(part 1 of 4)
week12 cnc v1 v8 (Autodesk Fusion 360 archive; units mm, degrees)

design "week12 cnc v1" references "dollhome_wall_cnc", "Component3"
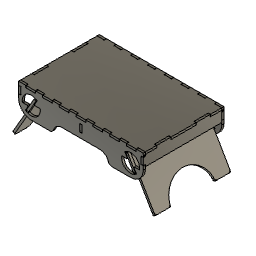
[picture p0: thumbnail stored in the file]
parameter "toplength" = 695.427
sketch "Sketch1" plane through (0, 0, 0) normal (0, 1, 0) x axis (1, 0, 0)
  line L1 (695.4269, 0) -> (0, 0)
  line L2 (695.4269, -141.0037) -> (695.4269, 0)
  line L3 (0, -141.0037) -> (695.4269, -141.0037)
  line L4 (0, 0) -> (0, -141.0037)
  line L5 (192.7135, 0) -> (22.7135, 0)
  line L6 (347.7135, -50) -> (242.7135, -50)
  line L7 (347.7135, 0) -> (347.7135, -141.0037)
  line L8 (502.7135, 0) -> (672.7135, 0)
  line L9 (347.7135, -50) -> (452.7135, -50)
  arc A1 centre (242.7135, 0) radius 50 clockwise from (242.7135, -50) to (192.7135, 0)
  arc A2 centre (452.7135, 0) radius 50 clockwise from (502.7135, 0) to (452.7135, -50)
  circle C1 centre (624.9251, -70.5018) radius 50
  circle C2 centre (70.5018, -70.5018) radius 50
  circle C3 centre (624.9251, -70.5018) radius 70.5018
  circle C4 centre (70.5018, -70.5018) radius 70.5018
  point P1 (0, 0)
  point P2 (0, 0)
  point P6 (22.7135, 0)
  point P7 (192.7135, 0)
  point P11 (347.7135, -141.0037)
  point P12 (347.7135, 0)
  point P13 (672.7135, 0)
  point P15 (502.7135, 0)
  point P8 (242.7135, -50)
  point P16 (452.7135, -50)
  point P10 (347.7135, -50)
  point P17 (347.7135, -50)
  point P9 (242.7135, 0)
  point P14 (452.7135, 0)
  point P4 (695.4269, -141.0037)
  point P5 (0, -141.0037)
  horizontal L1
  vertical L2
  horizontal L3
  vertical L4
  coincident P1 P2
  coincident L1 P6
  coincident L1 P7
  midpoint L3 P11
  midpoint L1 P12
  symmetric P6 L7 P13
  symmetric P7 L7 P15
  symmetric P8 L7 P16
  symmetric A1 L7 A2
  symmetric P10 L7 P17
  symmetric L7 C1 C2
  coincident L1 P9
  tangent A2 L9
  coincident P10 P17
  perpendicular L6 L7
  concentric C1 C3
  tangent L1 C3
  tangent L3 C3
  tangent L2 C3
  concentric C2 C4
  tangent L1 C4
  dimension "d6" diameter C1 = 100
  dimension "d100" distance L1 L6 = 50
  dimension "d101" distance P9 P14 = 210
  dimension "d102" distance P4 P5 = 695.4269
sketch "Sketch5" plane through (0, 0, 0) normal (0, 0, 1) x axis (1, 0, 0)
  line L1 (695.427, 0) -> (0, 0)
  line L2 (695.427, 450) -> (695.427, 0)
  line L3 (0, 450) -> (695.427, 450)
  line L4 (0, 0) -> (0, 450)
  line L5 (695.427, 225) -> (0, 225)
  line L6 (347.7135, 0) -> (347.7135, 450)
  point P1 (0, 0)
  point P2 (0, 0)
  point P6 (0, 225)
  point P7 (695.427, 225)
  point P8 (347.7135, 450)
  point P9 (347.7135, 0)
  point P3 (695.427, 0)
  point P4 (695.427, 450)
  horizontal L1
  vertical L2
  horizontal L3
  vertical L4
  coincident P1 P2
  coincident L4 P6
  coincident L2 P7
  perpendicular L2 L5
  coincident L3 P8
  coincident L1 P9
  perpendicular L1 L6
  midpoint L5 L6
  dimension "d104" distance L2 L4 = 695.427 (= "toplength")
  dimension "d110" distance P3 P4 = 450
extrude "Extrude1" new body sketch "Sketch1" profile of L1 L2 L3 L4 L5 A1 L6 A2 L8 L9 C1 C2 C3 C4 no distance stored
extrude "Extrude1" sketch "Sketch5" profile of L1 L2 L3 L4 no distance stored
work_plane "WorkPlane2" AlongDistance 225
mirror_component "MirrorComponent2"
derived_instance "DerivedInstance2"
sketch "Sketch6" plane through (0, 0, 0) normal (0, 1, 0) x axis (1, 0, 0)
  line L1 (618.9251, -23.0018) -> (630.9251, -23.0018)
  line L2 (618.9251, -118.0018) -> (618.9251, -23.0018)
  line L3 (630.9251, -118.0018) -> (618.9251, -118.0018)
  line L4 (630.9251, -23.0018) -> (630.9251, -118.0018)
  line L5 (618.9251, -118.0018) -> (630.9251, -23.0018)
  line L6 (630.9251, -118.0018) -> (618.9251, -23.0018)
  line L7 (347.7135, 0) -> (347.7135, -141.0037)
  line L8 (64.5018, -118.0018) -> (76.5018, -118.0018)
  line L9 (76.5018, -118.0018) -> (76.5018, -23.0018)
  line L10 (64.5018, -23.0018) -> (64.5018, -118.0018)
  line L11 (76.5018, -23.0018) -> (64.5018, -23.0018)
  line L12 (64.5018, -118.0018) -> (76.5018, -23.0018)
  line L13 (76.5018, -118.0018) -> (64.5018, -23.0018)
  line L14 (0, 0) -> (0, -150)
  point P6 (624.9251, -70.5018)
  point P7 (624.9251, -70.5018)
  point P2 (630.9251, -23.0018)
  point P12 (64.5018, -23.0018)
  point P3 (618.9251, -23.0018)
  point P15 (76.5018, -23.0018)
  point P4 (618.9251, -118.0018)
  point P10 (76.5018, -118.0018)
  point P5 (630.9251, -118.0018)
  point P11 (64.5018, -118.0018)
  point P14 (70.5018, -70.5018)
  point P13 (70.5018, -70.5018)
  point P1 (0, 0)
  point P17 (0, 0)
  horizontal L1
  perpendicular L1 L2
  parallel L1 L3
  parallel L2 L4
  coincident L5 P6
  coincident L6 P6
  coincident P6 P7
  symmetric P2 L7 P12
  symmetric P3 L7 P15
  symmetric P4 L7 P10
  symmetric P5 L7 P11
  symmetric P6 L7 P14
  symmetric P7 L7 P13
  vertical L14
  coincident P1 P17
  dimension "d112" distance P3 P4 = 95
  dimension "d113" distance P4 P5 = 12 (= "Linear Dimension-3")
sketch "Sketch9" plane through (0, 0, 0) normal (1, 0, 0) x axis (0, 1, 0)
  line L1 (76.9446, 118.0018) -> (0, 118.0018)
  line L2 (80, 23.0018) -> (0, 23.0018)
  line L3 (117.9773, 70.5018) -> (0, 70.5018)
  point P2 (0, 118.0018)
  point P3 (0, 118.0018)
  point P5 (0, 23.0018)
  point P6 (0, 23.0018)
  point P8 (0, 70.5018)
  point P9 (0, 70.5018)
  coincident P2 P3
  horizontal L1
  coincident P5 P6
  horizontal L2
  coincident P8 P9
  horizontal L3
work_plane "WorkPlane3" AlongDistance 70.502
sketch "Sketch12" plane through (70.502, 0, 0) normal (1, 0, 0) x axis (0, 1, 0)
  line L1 (436, 135) -> (14, 135)
  line L2 (436, -165) -> (436, 135)
  line L3 (14, -165) -> (436, -165)
  line L4 (14, 135) -> (14, -165)
  line L5 (450, 141.0037) -> (0, 141.0037)
  line L6 (438, 70.5018) -> (438, 0)
  line L7 (225, -154.225) -> (225, 154.225)
  line L8 (0, 0) -> (450, 0)
  line L9 (12, 0) -> (12, 141.0037)
  line L10 (12, 0) -> (0, 0)
  line L11 (0, 0) -> (0, 141.0037)
  arc A1 centre (225.1382, -175.6217) radius 125.5882 clockwise from (100, -165) to (350.2765, -165)
  point P15 (100, -165)
  point P14 (350.2765, -165)
  point P18 (12, 141.0037)
  point P19 (12, 0)
  point P1 (0, 0)
  point P20 (0, 0)
  point P2 (14, 135)
  point P17 (14, 135)
  point P3 (436, 135)
  point P4 (436, -165)
  point P11 (225, -154.225)
  point P16 (225.1382, -175.6217)
  horizontal L1
  vertical L2
  horizontal L3
  vertical L4
  perpendicular L3 L7
  midpoint L7 L8
  coincident L3 P15
  coincident L3 P14
  coincident L5 P18
  coincident L8 P19
  coincident P1 P20
  vertical L9
  coincident P2 P17
  dimension "d120" distance L1 L5 = 6.0037
  dimension "d121" distance P3 P4 = 300
  dimension "d122" distance L2 L6 = 2
  dimension "d123" distance P11 P16 = 21.3972
  dimension "d124" distance P14 P15 = 250.2765
  dimension "d380" distance L9 L11 = 12
  dimension "d381" distance L4 L9 = 2
extrude "Extrude1" new body sketch "Sketch12" profile of L1 L2 L3 L4 L8 A1 no distance stored
extrude "Extrude2" new body sketch "Sketch6" profile of L8 L9 L10 L11 to an object
work_plane "WorkPlane4" AlongDistance 347.714
mirror_component "MirrorComponent3"
derived_instance "DerivedInstance3"
joint "Assemble8" alignAngle 210 alignOffsetX 0 alignOffsetY 0 alignOffsetZ 0
sketch "Sketch13" plane through (0, 0, 0) normal (0, 0, 1) x axis (1, 0, 0)
  line L1 (40, 12) -> (0, 12)
  line L2 (40, 0) -> (40, 12)
  line L3 (0, 0) -> (40, 0)
  line L4 (0, 12) -> (0, 0)
  line L5 (0, 0) -> (0, 450)
  line L6 (695.427, 0) -> (0, 0)
  line L7 (133.6429, 12) -> (93.6429, 12)
  line L8 (93.6429, 12) -> (93.6429, 0)
  line L9 (133.6429, 0) -> (133.6429, 12)
  line L10 (93.6429, 0) -> (133.6429, 0)
  line L11 (227.2857, 12) -> (187.2857, 12)
  line L12 (187.2857, 12) -> (187.2857, 0)
  line L13 (227.2857, 0) -> (227.2857, 12)
  line L14 (187.2857, 0) -> (227.2857, 0)
  line L15 (320.9286, 12) -> (280.9286, 12)
  line L16 (280.9286, 12) -> (280.9286, 0)
  line L17 (320.9286, 0) -> (320.9286, 12)
  line L18 (280.9286, 0) -> (320.9286, 0)
  line L19 (414.5714, 12) -> (374.5714, 12)
  line L20 (374.5714, 12) -> (374.5714, 0)
  line L21 (414.5714, 0) -> (414.5714, 12)
  line L22 (374.5714, 0) -> (414.5714, 0)
  line L23 (508.2143, 12) -> (468.2143, 12)
  line L24 (468.2143, 12) -> (468.2143, 0)
  line L25 (508.2143, 0) -> (508.2143, 12)
  line L26 (468.2143, 0) -> (508.2143, 0)
  line L27 (601.8571, 12) -> (561.8571, 12)
  line L28 (561.8571, 12) -> (561.8571, 0)
  line L29 (601.8571, 0) -> (601.8571, 12)
  line L30 (561.8571, 0) -> (601.8571, 0)
  line L31 (695.5, 12) -> (655.5, 12)
  line L32 (655.5, 12) -> (655.5, 0)
  line L33 (695.5, 0) -> (695.5, 12)
  line L34 (655.5, 0) -> (695.5, 0)
  line L35 (695.427, 225) -> (0, 225)
  line L36 (320.9286, 450) -> (320.9286, 438)
  line L37 (468.2143, 438) -> (468.2143, 450)
  line L38 (227.2857, 438) -> (187.2857, 438)
  line L39 (40, 450) -> (40, 438)
  line L40 (93.6429, 450) -> (133.6429, 450)
  line L41 (133.6429, 450) -> (133.6429, 438)
  line L42 (133.6429, 438) -> (93.6429, 438)
  line L43 (93.6429, 438) -> (93.6429, 450)
  line L44 (0, 450) -> (40, 450)
  line L45 (40, 438) -> (0, 438)
  line L46 (0, 438) -> (0, 450)
  line L47 (561.8571, 450) -> (601.8571, 450)
  line L48 (227.2857, 450) -> (227.2857, 438)
  line L49 (508.2143, 450) -> (508.2143, 438)
  line L50 (655.5, 438) -> (655.5, 450)
  line L51 (695.5, 450) -> (695.5, 438)
  line L52 (414.5714, 438) -> (374.5714, 438)
  line L53 (601.8571, 450) -> (601.8571, 438)
  line L54 (655.5, 450) -> (695.5, 450)
  line L55 (414.5714, 450) -> (414.5714, 438)
  line L56 (320.9286, 438) -> (280.9286, 438)
  line L57 (695.5, 438) -> (655.5, 438)
  line L58 (508.2143, 438) -> (468.2143, 438)
  line L59 (601.8571, 438) -> (561.8571, 438)
  line L60 (374.5714, 438) -> (374.5714, 450)
  line L61 (468.2143, 450) -> (508.2143, 450)
  line L62 (561.8571, 438) -> (561.8571, 450)
  line L63 (187.2857, 438) -> (187.2857, 450)
  line L64 (187.2857, 450) -> (227.2857, 450)
  line L65 (280.9286, 450) -> (320.9286, 450)
  line L66 (695.427, 450) -> (0, 450)
  line L67 (280.9286, 438) -> (280.9286, 450)
  line L68 (374.5714, 450) -> (414.5714, 450)
  point P4 (40, 0)
  point P2 (0, 12)
  point P1 (0, 0)
  point P57 (0, 450)
  point P67 (0, 438)
  point P3 (40, 12)
  point P56 (40, 438)
  point P58 (40, 450)
  point P5 (0, 0)
  point P55 (0, 450)
  point P7 (0, 0)
  point P68 (0, 450)
  point P8 (695.427, 0)
  point P59 (695.427, 450)
  point P9 (93.6429, 12)
  point P54 (93.6429, 438)
  point P10 (133.6429, 12)
  point P53 (133.6429, 438)
  point P11 (93.6429, 0)
  point P52 (93.6429, 450)
  point P12 (133.6429, 0)
  point P66 (133.6429, 450)
  point P13 (187.2857, 12)
  point P65 (187.2857, 438)
  point P14 (227.2857, 12)
  point P64 (227.2857, 438)
  point P15 (187.2857, 0)
  point P63 (187.2857, 450)
  point P16 (227.2857, 0)
  point P62 (227.2857, 450)
  point P17 (280.9286, 12)
  point P61 (280.9286, 438)
  point P18 (320.9286, 12)
  point P49 (320.9286, 438)
  point P19 (280.9286, 0)
  point P60 (280.9286, 450)
  point P20 (320.9286, 0)
  point P44 (320.9286, 450)
  point P21 (374.5714, 12)
  point P73 (374.5714, 438)
  point P22 (414.5714, 12)
  point P46 (414.5714, 438)
  point P23 (374.5714, 0)
  point P70 (374.5714, 450)
  point P24 (414.5714, 0)
  point P72 (414.5714, 450)
  point P25 (468.2143, 12)
  point P47 (468.2143, 438)
  point P26 (508.2143, 12)
  point P51 (508.2143, 438)
  point P27 (468.2143, 0)
  point P71 (468.2143, 450)
  point P28 (508.2143, 0)
  point P69 (508.2143, 450)
  point P29 (561.8571, 12)
  point P50 (561.8571, 438)
  point P30 (601.8571, 12)
  point P45 (601.8571, 438)
  point P31 (561.8571, 0)
  point P41 (561.8571, 450)
  point P32 (601.8571, 0)
  point P40 (601.8571, 450)
  point P33 (655.5, 12)
  point P48 (655.5, 438)
  point P34 (695.5, 12)
  point P42 (695.5, 438)
  point P35 (655.5, 0)
  point P39 (655.5, 450)
  point P36 (695.5, 0)
  point P43 (695.5, 450)
  horizontal L1
  vertical L2
  horizontal L3
  vertical L4
  coincident P4 L6
  coincident P2 L5
  symmetric P1 L35 P57
  symmetric P2 L35 P67
  symmetric P3 L35 P56
  symmetric P4 L35 P58
  symmetric P5 L35 P55
  symmetric P7 L35 P68
  symmetric P8 L35 P59
  symmetric P9 L35 P54
  symmetric P10 L35 P53
  symmetric P11 L35 P52
  symmetric P12 L35 P66
  symmetric P13 L35 P65
  symmetric P14 L35 P64
  symmetric P15 L35 P63
  symmetric P16 L35 P62
  symmetric P17 L35 P61
  symmetric P18 L35 P49
  symmetric P19 L35 P60
  symmetric P20 L35 P44
  symmetric P21 L35 P73
  symmetric P22 L35 P46
  symmetric P23 L35 P70
  symmetric P24 L35 P72
  symmetric P25 L35 P47
  symmetric P26 L35 P51
  symmetric P27 L35 P71
  symmetric P28 L35 P69
  symmetric P29 L35 P50
  symmetric P30 L35 P45
  symmetric P31 L35 P41
  symmetric P32 L35 P40
  symmetric P33 L35 P48
  symmetric P34 L35 P42
  symmetric P35 L35 P39
  symmetric P36 L35 P43
  dimension "d138" distance L2 L4 = 40
  dimension "d377" distance L1 L3 = 12 (= "Linear Dimension-3")
  dimension "d141" R-Pattern1-uDistance = 655.5
  dimension "d142" R-Pattern1-vDistance = 0
sketch "Sketch14" plane through (0, 0, 0) normal (0, 0, 1) x axis (1, 0, 0)
  line L1 (695.4269, 0) -> (0, 0)
  line L2 (695.4269, 12) -> (695.4269, 0)
  line L3 (0, 12) -> (695.4269, 12)
  line L4 (0, 0) -> (0, 12)
extrude "Extrude2" sketch "Sketch13" profile of L1 L2 L3 L4 L5 L6 L7 L8 L9 L10 L11 L12 L13 L14 L15 L16 L17 L18 L19 L20 L21 L22 L23 L24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 no distance stored
extrude "Extrude1" sketch "Sketch13" profile of L5 L36 L37 L38 L39 L40 L41 L42 L43 L44 L45 L46 L47 L48 L49 L50 L51 L52 L53 L54 L55 L56 L57 L58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 no distance stored
sketch "Sketch24" plane through (0, 0, 153.0037) normal (0, 0, 1) x axis (-1, 0, 0)
  line L1 (0, -450) -> (-695.427, -450)
  line L2 (0, 0) -> (0, -450)
  line L3 (-695.427, 0) -> (0, 0)
  line L4 (-695.427, -450) -> (-695.427, 0)
joint "Assemble9" alignAngle 0 alignOffsetX 0 alignOffsetY 0 alignOffsetZ 0 RotateMinimum 30 RotateMaximum 90 RotateRest 30
extrude "Extrude2" sketch "Sketch13" profile of L1 L2 L3 L4 L5 L6 L7 L8 L9 L10 L11 L12 L13 L14 L15 L16 L17 L18 L19 L20 L21 L22 L23 L24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 no distance stored
position "Position2" RotateAboutZ -60 RotateAboutZ 30
sketch "Sketch15" plane through (0, 0, 0) normal (0, 1, 0) x axis (1, 0, 0)
  line L1 (13.1164, -32.418) -> (38.1164, -32.4224)
  line L2 (0.6125, -54.0664) -> (13.1164, -32.418)
  line L3 (13.1087, -75.7192) -> (0.6125, -54.0664)
  line L4 (38.1087, -75.7237) -> (13.1087, -75.7192)
  line L5 (50.6125, -54.0752) -> (38.1087, -75.7237)
  line L6 (38.1164, -32.4224) -> (50.6125, -54.0752)
  line L7 (127.8936, -108.5819) -> (102.8936, -108.5909)
  line L8 (140.3858, -86.9267) -> (127.8936, -108.5819)
  line L9 (127.878, -65.2806) -> (140.3858, -86.9267)
  line L10 (102.878, -65.2896) -> (127.878, -65.2806)
  line L11 (90.3858, -86.9447) -> (102.878, -65.2896)
  line L12 (102.8936, -108.5909) -> (90.3858, -86.9447)
  line L13 (0.6125, -54.0664) -> (50.6125, -54.0752)
  line L14 (140.3858, -86.9267) -> (90.3858, -86.9447)
  circle C1 centre (70.5018, -70.5018) radius 50
  point P9 (102.8936, -108.5909)
  point P2 (38.1164, -32.4224)
  point P7 (50.6125, -54.0752)
  point P14 (90.3858, -86.9447)
  coincident P9 C1
  dimension "d158" distance P2 P7 = 25
  dimension "d159" distance P9 P14 = 25
extrude "Extrude4" new body sketch "Sketch15" profile of L1 L6 L12 C1 L13 L14 no distance stored
position "Position3" RotateAboutZ -90
extrude "Extrude5" add of existing geometry blind 7
extrude "Extrude6" add of existing geometry blind 3
extrude "Extrude7" add of existing geometry blind 7
extrude "Extrude8" add of existing geometry blind 3
mirror "Mirror1" mirrorStitchTolerance 0.1
work_plane "WorkPlane5"
mirror "Mirror2" mirrorStitchTolerance 0.1
mirror "Mirror3" mirrorStitchTolerance 0.1
component_from_bodies "Body->Comp4"
component_from_bodies "Body->Comp5"
component_from_bodies "Body->Comp6"
component_from_bodies "Body->Comp7"
component_from_bodies "Body->Comp8"
component_from_bodies "Body->Comp9"
component_from_bodies "Body->Comp10"
component_from_bodies "Body->Comp11"
work_plane "WorkPlane7"
mirror "Mirror2" mirrorStitchTolerance 0.1
combine "Combine1"
combine "Combine1"
combine "Combine3"
fillet "Fillet1" radius 5
fillet "Fillet2" radius 5
fillet "Fillet1" radius 20
work_plane "WorkPlane8"
work_plane "WorkPlane9"
mirror "Mirror1" mirrorStitchTolerance 0.1
mirror "Mirror3" mirrorStitchTolerance 0.1
sketch "Sketch26" plane through (347.7135, 0, 0) normal (-1, 0, 0) x axis (0, -1, 0)
  line L1 (-438, 70.5018) -> (-438, 141.0037)
  line L2 (-12, 70.5018) -> (-12, 141.0037)
  line L3 (-450, 118.306) -> (-438, 118.306)
  line L4 (-450, 78.306) -> (-450, 118.306)
  line L5 (-438, 78.306) -> (-450, 78.306)
  line L6 (-12, 133.306) -> (-438, 133.306)
  line L7 (-12, 70.5018) -> (-438, 70.5018)
  line L8 (-225, 70.5018) -> (-225, 133.306)
  line L9 (0, 118.306) -> (-12, 118.306)
  line L10 (0, 78.306) -> (0, 118.306)
  line L11 (-12, 78.306) -> (0, 78.306)
  point P6 (-438, 118.306)
  point P9 (-438, 78.306)
  point P10 (-438, 133.306)
  point P11 (-12, 133.306)
  point P3 (-438, 70.5018)
  point P12 (-438, 70.5018)
  point P5 (-12, 70.5018)
  point P13 (-12, 70.5018)
  point P14 (-225, 133.306)
  point P15 (-225, 70.5018)
  point P16 (-12, 118.306)
  point P7 (-450, 118.306)
  point P17 (0, 118.306)
  point P8 (-450, 78.306)
  point P18 (0, 78.306)
  point P19 (-12, 78.306)
  coincident L1 P6
  perpendicular L1 L3
  perpendicular L3 L4
  coincident L1 P9
  perpendicular L1 L5
  coincident L1 P10
  coincident L2 P11
  perpendicular L2 L6
  coincident P3 P12
  coincident P5 P13
  midpoint L6 P14
  midpoint L7 P15
  symmetric P6 L8 P16
  symmetric P7 L8 P17
  symmetric P8 L8 P18
  symmetric P9 L8 P19
  dimension "d394" distance P6 L6 = 15
  dimension "d395" distance P6 P7 = 12 (= "Linear Dimension-3")
  dimension "d398" distance P7 P8 = 40
extrude "Extrude15" new body sketch "Sketch26" profile of L1 L2 L3 L4 L5 L6 L7 L9 L10 L11 no distance stored
combine "Combine2"
combine "Combine3"
sketch "Sketch27" plane through (0, 0, 0) normal (-1, 0, 0) x axis (0, -1, 0)
  line L1 (-12, 153.0037) -> (-12, 141.0037)
  line L2 (-438, 153.0037) -> (-12, 153.0037)
  line L3 (-438, 141.0037) -> (-438, 153.0037)
  line L4 (-12, 153.0037) -> (-438, 153.0037)
  line L5 (-450, 70.5018) -> (-450, 153.0037)
  line L6 (0, 70.5018) -> (0, 153.0037)
  line L7 (-225, -203.8085) -> (-225, 153.0037)
  line L8 (0, 111.7528) -> (-450, 111.7528)
  line L9 (-375, 141.0037) -> (-375, 153.0037)
  line L10 (-295, 141.0037) -> (-295, 153.0037)
  line L11 (-155, 141.0037) -> (-155, 153.0037)
  line L12 (-75, 141.0037) -> (-75, 153.0037)
  line L13 (-438, 131.7528) -> (-450, 131.7528)
  line L14 (-438, 91.7528) -> (-450, 91.7528)
  line L15 (-12, 131.7528) -> (0, 131.7528)
  line L16 (-12, 91.7528) -> (0, 91.7528)
  line L17 (-438, 141.0037) -> (-438, 131.7528)
  line L18 (-438, 141.0037) -> (-375, 141.0037)
  line L19 (-155, 141.0037) -> (-295, 141.0037)
  line L20 (-438, 81.7528) -> (-438, 91.7528)
  line L21 (-12, 81.7528) -> (-438, 81.7528)
  line L22 (-12, 91.7528) -> (-12, 81.7528)
  line L23 (-450, 91.7528) -> (-450, 131.7528)
  line L24 (0, 91.7528) -> (0, 131.7528)
  line L25 (-12, 131.7528) -> (-12, 141.0037)
  line L26 (-12, 141.0037) -> (-75, 141.0037)
  point P12 (-225, 153.0037)
  point P14 (-450, 111.7528)
  point P15 (0, 111.7528)
  point P16 (-375, 153.0037)
  point P18 (-295, 153.0037)
  point P20 (-155, 153.0037)
  point P22 (-75, 153.0037)
  point P24 (-450, 131.7528)
  point P26 (-450, 91.7528)
  point P28 (0, 131.7528)
  point P25 (-438, 131.7528)
  point P29 (-12, 131.7528)
  point P30 (0, 91.7528)
  point P27 (-438, 91.7528)
  point P31 (-12, 91.7528)
  point P5 (-438, 141.0037)
  point P32 (-438, 141.0037)
  point P33 (-438, 141.0037)
  point P2 (-12, 141.0037)
  point P36 (-12, 141.0037)
  point P17 (-375, 141.0037)
  point P19 (-295, 141.0037)
  point P21 (-155, 141.0037)
  point P23 (-75, 141.0037)
  midpoint L4 P12
  midpoint L5 P14
  midpoint L6 P15
  coincident L2 P16
  coincident L4 P18
  coincident L4 P20
  coincident L4 P22
  coincident L5 P24
  perpendicular L5 L13
  coincident L5 P26
  perpendicular L5 L14
  symmetric L7 P24 P28
  symmetric L7 P25 P29
  symmetric L7 P26 P30
  symmetric L7 P27 P31
  coincident P5 P32
  coincident P5 P33
  perpendicular L17 L18
  vertical L7
  vertical L12
  perpendicular L14 L20
  perpendicular L20 L21
  vertical L22
  coincident P2 P36
  dimension "d399" distance P24 P25 = 12 (= "Linear Dimension-2")
  dimension "d400" distance P26 P27 = 12 (= "Linear Dimension-3")
  dimension "d401" distance L8 L13 = 20
  dimension "d402" distance L8 L14 = 20
  dimension "d403" distance L7 P18 = 70
  dimension "d404" distance P12 P20 = 70
  dimension "d405" distance L9 L10 = 80
  dimension "d406" distance L11 L12 = 80
  dimension "d407" distance P16 P17 = 12 (= "Linear Dimension-10")
  dimension "d408" distance P18 P19 = 12 (= "Linear Dimension-11")
  dimension "d409" distance P20 P21 = 12 (= "Linear Dimension-12")
  dimension "d410" distance P22 P23 = 12 (= "Linear Dimension-13")
  dimension "d411" distance P27 L21 = 10
extrude "Extrude16" new body sketch "Sketch27" profile of L2 L4 L5 L6 L9 L10 L11 L12 L13 L14 L15 L16 L17 L18 L19 L20 L21 L22 L23 L24 L25 L26 no distance stored
combine "Combine4"
combine "Combine4"
combine "Combine5"
mirror "Mirror4" mirrorStitchTolerance 0.1
combine "Combine5"
combine "Combine6"
combine "Combine7"
component_from_bodies "Body->Comp1"
component_from_bodies "Body->Comp2"
component_from_bodies "Body->Comp1"
component_from_bodies "Body->Comp2"
component_from_bodies "Body->Comp14"
component_from_bodies "Body->Comp15"
component_from_bodies "Body->Comp16"
step "Arrange7" AngleFromX 0 Priority 500 AngleFromX 0 Priority 500 AngleFromX 0 Priority 500 AngleFromX 0 Priority 500 AngleFromX 0 Priority 500 AngleFromX 0 Priority 500 AngleFromX 0 Priority 500 AngleFromX 0 Priority 500 originOffsetX 1300 originOffsetY 0 envelopeLength 2438.4 envelopeWidth 1219.2 envelopeSpacing 0 grainDirection 0 objectSpacing 15 frameWidth 30 placementClearance 0
fillet "Fillet1" radius 15
work_plane "WorkPlane10"
sketch "Sketch28" plane through (1368.1164, 62.4225, 0) normal (0, 0, 1) x axis (1, 0, 0)
  line L1 (-0.0175, 0) -> (0, 0)
  line L2 (0, 0) -> (12.4962, 21.6528)
  line L3 (2.5978, 1.5005) -> (0, 0)
  circle C1 centre (2.5978, 1.5005) radius 3
  point P2 (0, 0)
  point P5 (0, 0)
  point P6 (2.5978, 1.5005)
  coincident P2 P5
  coincident P5 C1
  dimension "d448" distance P5 P6 = 3 (= "6 mm / 2")
sweep "Sweep1" sketch "Sketch28" TwistAngle 0 TaperAngle 0
work_plane "WorkPlane11"
sketch "Sketch29" plane through (1351.3995, 91.0701, 0) normal (0, 0, 1) x axis (1, 0, 0)
  line L1 (0, 0) -> (29.2118, 0.0052)
  line L2 (54.353, 22.763) -> (0, 0)
  arc A1 centre (49.1024, 9.4318) radius 50 clockwise from (0, 0) to (81.4941, 47.5208)
  point P3 (0, 0)
  point P6 (0, 0)
  coincident P3 P6
base_feature "Base Feature10" bodies "Dogbones"
combine "Combine6"
base_feature "Base Feature11" bodies "Dogbones (1)"
combine "Combine1"
base_feature "Base Feature12" bodies "Dogbones (2)"
combine "Combine2"
base_feature "Base Feature13" bodies "Dogbones (3)"
combine "Combine3"
base_feature "Base Feature14" bodies "Dogbones (4)"
combine "Combine4"
base_feature "Base Feature15" bodies "Dogbones (5)"
combine "Combine7"
base_feature "Base Feature16" bodies "Dogbones (6)"
combine "Combine5"
base_feature "Base Feature17" bodies "Dogbones (7)"
combine "Combine8"
base_feature "Base Feature18" bodies "Dogbones (8)"
combine "Combine1"
base_feature "Base Feature19" bodies "Dogbones (9)"
combine "Combine9"
base_feature "Base Feature20" bodies "Dogbones (10)"
combine "Combine1"
base_feature "Base Feature21" bodies "Dogbones (11)"
combine "Combine10"
base_feature "Base Feature22" bodies "Dogbones (12)"
combine "Combine1"
sketch "Sketch30" plane through (0, 0, 12) normal (0, 0, 1) x axis (-1, 0, 0)
  line L1 (-1342.073, -688.5332) -> (-1342.073, -719.9761)
  line L2 (-1330.0731, -684.2546) -> (-1337.7945, -684.2546)
  line L3 (-1330.0731, -675.0037) -> (-1330.0731, -684.2546)
  line L4 (-1330, -675.0037) -> (-1330.0731, -675.0037)
  line L5 (-1330, -663.0037) -> (-1330, -675.0037)
  line L6 (-1370, -663.0037) -> (-1330, -663.0037)
  line L7 (-1370, -675.0037) -> (-1370, -663.0037)
  line L8 (-1419.3643, -675.0037) -> (-1370, -675.0037)
  line L9 (-1423.6429, -663.0037) -> (-1423.6429, -670.7251)
  line L10 (-1463.6429, -663.0037) -> (-1423.6429, -663.0037)
  line L11 (-1463.6429, -670.7251) -> (-1463.6429, -663.0037)
  line L12 (-1513.0072, -675.0037) -> (-1467.9214, -675.0037)
  line L13 (-1517.2857, -663.0037) -> (-1517.2857, -670.7251)
  line L14 (-1557.2857, -663.0037) -> (-1517.2857, -663.0037)
  line L15 (-1557.2857, -670.7251) -> (-1557.2857, -663.0037)
  line L16 (-1606.65, -675.0037) -> (-1561.5643, -675.0037)
  line L17 (-1610.9286, -663.0037) -> (-1610.9286, -670.7251)
  line L18 (-1650.9286, -663.0037) -> (-1610.9286, -663.0037)
  line L19 (-1650.9286, -670.7251) -> (-1650.9286, -663.0037)
  line L20 (-1700.2929, -675.0037) -> (-1655.2072, -675.0037)
  line L21 (-1704.5715, -663.0037) -> (-1704.5715, -670.7251)
  line L22 (-1744.5715, -663.0037) -> (-1704.5715, -663.0037)
  line L23 (-1744.5715, -670.7251) -> (-1744.5715, -663.0037)
  line L24 (-1793.9358, -675.0037) -> (-1748.85, -675.0037)
  line L25 (-1798.2143, -663.0037) -> (-1798.2143, -670.7251)
  line L26 (-1838.2143, -663.0037) -> (-1798.2143, -663.0037)
  line L27 (-1838.2143, -670.7251) -> (-1838.2143, -663.0037)
  line L28 (-1887.5786, -675.0037) -> (-1842.4929, -675.0037)
  line L29 (-1891.8572, -663.0037) -> (-1891.8572, -670.7251)
  line L30 (-1931.8572, -663.0037) -> (-1891.8572, -663.0037)
  line L31 (-1931.8572, -670.7251) -> (-1931.8572, -663.0037)
  line L32 (-1981.2215, -675.0037) -> (-1936.1357, -675.0037)
  line L33 (-1985.5, -663.0037) -> (-1985.5, -670.7251)
  line L34 (-2025.5, -663.0037) -> (-1985.5, -663.0037)
  line L35 (-2025.5, -684.2546) -> (-2025.5, -663.0037)
  line L36 (-2013.5, -684.2546) -> (-2025.5, -684.2546)
  line L37 (-2013.5, -724.2546) -> (-2013.5, -684.2546)
  line L38 (-2025.5, -724.2546) -> (-2013.5, -724.2546)
  line L39 (-2025.5, -745.5056) -> (-2025.5, -724.2546)
  line L40 (-1849.8686, -816.0074) -> (-1954.9982, -816.0074)
  line L41 (-1572.7866, -766.0074) -> (-1782.7866, -766.0074)
  line L42 (-1400.575, -816.0074) -> (-1505.7045, -816.0074)
  line L43 (-1330.0731, -724.2546) -> (-1330.0731, -745.5055)
  line L44 (-1337.7945, -724.2546) -> (-1330.0731, -724.2546)
  line L45 (-1987.3837, -783.585) -> (-1987.4012, -783.585)
  line L46 (-1974.8875, -761.9321) -> (-1987.3837, -783.585)
  line L47 (-1974.8888, -754.9321) -> (-1974.8875, -761.9321)
  line L48 (-2004.1006, -754.9373) -> (-1974.8888, -754.9321)
  line L49 (-1935.1142, -729.0627) -> (-1924.5451, -710.7716)
  line L50 (-1935.1168, -736.0627) -> (-1935.1142, -729.0627)
  line L51 (-1909.749, -736.0718) -> (-1935.1168, -736.0627)
  line L52 (-1420.4563, -736.0627) -> (-1449.6772, -736.0732)
  line L53 (-1420.4588, -729.0627) -> (-1420.4563, -736.0627)
  line L54 (-1432.9666, -707.4165) -> (-1420.4588, -729.0627)
  line L55 (-1447.7974, -729.0725) -> (-1447.7973, -729.0725)
  line L56 (-1380.6843, -754.9321) -> (-1351.4726, -754.9373)
  line L57 (-1380.6855, -761.9321) -> (-1380.6843, -754.9321)
  line L58 (-1368.1894, -783.585) -> (-1380.6855, -761.9321)
  line L59 (-1368.1719, -783.585) -> (-1368.1894, -783.585)
  line L60 (-1671.7865, -737.7014) -> (-1671.7865, -697.7014)
  line L61 (-1683.7865, -737.7014) -> (-1671.7865, -737.7014)
  line L62 (-1683.7865, -697.7014) -> (-1683.7865, -737.7014)
  line L63 (-1671.7865, -697.7014) -> (-1683.7865, -697.7014)
  line L64 (-1434.7562, -704.3195) -> (-1431.5367, -709.8912)
  line L65 (-1455.022, -712.8044) -> (-1434.7562, -704.3195)
  line L66 (-1450.26, -732.3009) -> (-1455.022, -712.8044)
  line L67 (-1436.646, -727.5949) -> (-1450.26, -732.3009)
  line L68 (-1431.5367, -709.8912) -> (-1436.646, -727.5949)
  arc A1 centre (-1339.9337, -722.1154) radius 3.0254 clockwise from (-1337.7945, -724.2546) to (-1342.073, -719.9761)
  arc A2 centre (-1339.9337, -686.3939) radius 3.0254 clockwise from (-1342.073, -688.5332) to (-1337.7945, -684.2546)
  arc A3 centre (-1421.5036, -672.8644) radius 3.0254 clockwise from (-1419.3643, -675.0037) to (-1423.6429, -670.7251)
  arc A4 centre (-1465.7822, -672.8644) radius 3.0254 clockwise from (-1463.6429, -670.7251) to (-1467.9214, -675.0037)
  arc A5 centre (-1515.1465, -672.8644) radius 3.0254 clockwise from (-1513.0072, -675.0037) to (-1517.2857, -670.7251)
  arc A6 centre (-1559.425, -672.8644) radius 3.0254 clockwise from (-1557.2857, -670.7251) to (-1561.5643, -675.0037)
  arc A7 centre (-1608.7893, -672.8644) radius 3.0254 clockwise from (-1606.65, -675.0037) to (-1610.9286, -670.7251)
  arc A8 centre (-1653.0679, -672.8644) radius 3.0254 clockwise from (-1650.9286, -670.7251) to (-1655.2072, -675.0037)
  arc A9 centre (-1702.4322, -672.8644) radius 3.0254 clockwise from (-1700.2929, -675.0037) to (-1704.5715, -670.7251)
  arc A10 centre (-1746.7107, -672.8644) radius 3.0254 clockwise from (-1744.5715, -670.7251) to (-1748.85, -675.0037)
  arc A11 centre (-1796.075, -672.8644) radius 3.0254 clockwise from (-1793.9358, -675.0037) to (-1798.2143, -670.7251)
  arc A12 centre (-1840.3536, -672.8644) radius 3.0254 clockwise from (-1838.2143, -670.7251) to (-1842.4929, -675.0037)
  arc A13 centre (-1889.7179, -672.8644) radius 3.0254 clockwise from (-1887.5786, -675.0037) to (-1891.8572, -670.7251)
  arc A14 centre (-1933.9965, -672.8644) radius 3.0254 clockwise from (-1931.8572, -670.7251) to (-1936.1357, -675.0037)
  arc A15 centre (-1983.3607, -672.8644) radius 3.0254 clockwise from (-1981.2215, -675.0037) to (-1985.5, -670.7251)
  arc A16 centre (-1954.9982, -745.5055) radius 70.5018 clockwise from (-1954.9982, -816.0074) to (-2025.5, -745.5056)
  arc A17 centre (-1849.8686, -796.0074) radius 20 clockwise from (-1830.7023, -801.7217) to (-1849.8686, -816.0074)
  arc A18 centre (-1782.7866, -816.0074) radius 50 clockwise from (-1830.7023, -801.7217) to (-1782.7866, -766.0074)
  arc A19 centre (-1572.7866, -816.0074) radius 50 clockwise from (-1572.7866, -766.0074) to (-1524.8708, -801.7217)
  arc A20 centre (-1505.7045, -796.0074) radius 20 clockwise from (-1505.7045, -816.0074) to (-1524.8708, -801.7217)
  arc A21 centre (-1400.575, -745.5055) radius 70.5018 clockwise from (-1330.0731, -745.5055) to (-1400.575, -816.0074)
  arc A22 centre (-1907.8233, -738.4052) radius 3.0254 clockwise from (-1909.749, -736.0718) to (-1905.2949, -740.0665)
  arc A23 centre (-1954.9982, -745.5055) radius 50 clockwise from (-1905.2949, -740.0665) to (-1987.4012, -783.585)
  arc A24 centre (-1954.9982, -745.5055) radius 50 clockwise from (-2004.1006, -754.9373) to (-1925.8038, -704.9138)
  arc A25 centre (-1925.5877, -707.9315) radius 3.0254 clockwise from (-1925.8038, -704.9138) to (-1924.5451, -710.7716)
  arc A26 centre (-1400.575, -745.5055) radius 50 clockwise from (-1368.1719, -783.585) to (-1449.6772, -736.0732)
  arc A27 centre (-1400.5749, -745.5055) radius 50 clockwise from (-1447.7973, -729.0725) to (-1432.9666, -707.4165)
  arc A28 centre (-1400.575, -745.5055) radius 50 clockwise from (-1447.7974, -729.0725) to (-1351.4726, -754.9373)
  point P117 (-1431.5367, -709.8912)
  coincident L54 P117
extrude "Extrude2" add sketch "Sketch30" profile of A27 L55 A28 L64 to an object
base_feature "Base Feature23" bodies "Dogbones (13)"
combine "Combine2"
base_feature "Base Feature24" bodies "Dogbones (14)"
combine "Combine3"
base_feature "Base Feature25" bodies "Dogbones (15)"
combine "Combine4"
base_feature "Base Feature26" bodies "Dogbones (16)"
combine "Combine6"
base_feature "Base Feature27" bodies "Dogbones (17)"
combine "Combine5"
base_feature "Base Feature28" bodies "Dogbones1"
combine "Combine2"
base_feature "Base Feature29" bodies "Dogbones1 (1)"
combine "Combine1"
base_feature "Base Feature30" bodies "Dogbones1 (2)"
combine "Combine6"
sketch "Sketch31" plane through (0, 0, 12) normal (0, 0, 1) x axis (-1, 0, 0)
  line L1 (-2013.5, -719.9761) -> (-2013.5, -688.5332)
  line L2 (-2025.5, -724.2546) -> (-2017.7786, -724.2546)
  line L3 (-2025.5, -745.5056) -> (-2025.5, -724.2546)
  line L4 (-1849.8686, -816.0074) -> (-1954.9982, -816.0074)
  line L5 (-1572.7866, -766.0074) -> (-1782.7866, -766.0074)
  line L6 (-1400.575, -816.0074) -> (-1505.7045, -816.0074)
  line L7 (-1330.0731, -724.2546) -> (-1330.0731, -745.5055)
  line L8 (-1337.7945, -724.2546) -> (-1330.0731, -724.2546)
  line L9 (-1342.073, -688.5332) -> (-1342.073, -719.9761)
  line L10 (-1330.0731, -684.2546) -> (-1337.7945, -684.2546)
  line L11 (-1330.0731, -679.2823) -> (-1330.0731, -684.2546)
  line L12 (-1330, -663.0037) -> (-1330, -674.933)
  line L13 (-1370, -663.0037) -> (-1330, -663.0037)
  line L14 (-1370, -670.7251) -> (-1370, -663.0037)
  line L15 (-1419.3643, -675.0037) -> (-1374.2786, -675.0037)
  line L16 (-1423.6429, -663.0037) -> (-1423.6429, -670.7251)
  line L17 (-1463.6429, -663.0037) -> (-1423.6429, -663.0037)
  line L18 (-1463.6429, -670.7251) -> (-1463.6429, -663.0037)
  line L19 (-1513.0072, -675.0037) -> (-1467.9214, -675.0037)
  line L20 (-1517.2857, -663.0037) -> (-1517.2857, -670.7251)
  line L21 (-1557.2857, -663.0037) -> (-1517.2857, -663.0037)
  line L22 (-1557.2857, -670.7251) -> (-1557.2857, -663.0037)
  line L23 (-1606.65, -675.0037) -> (-1561.5643, -675.0037)
  line L24 (-1610.9286, -663.0037) -> (-1610.9286, -670.7251)
  line L25 (-1650.9286, -663.0037) -> (-1610.9286, -663.0037)
  line L26 (-1650.9286, -670.7251) -> (-1650.9286, -663.0037)
  line L27 (-1700.2929, -675.0037) -> (-1655.2072, -675.0037)
  line L28 (-1704.5715, -663.0037) -> (-1704.5715, -670.7251)
  line L29 (-1744.5715, -663.0037) -> (-1704.5715, -663.0037)
  line L30 (-1744.5715, -670.7251) -> (-1744.5715, -663.0037)
  line L31 (-1793.9358, -675.0037) -> (-1748.85, -675.0037)
  line L32 (-1798.2143, -663.0037) -> (-1798.2143, -670.7251)
  line L33 (-1838.2143, -663.0037) -> (-1798.2143, -663.0037)
  line L34 (-1838.2143, -670.7251) -> (-1838.2143, -663.0037)
  line L35 (-1887.5786, -675.0037) -> (-1842.4929, -675.0037)
  line L36 (-1891.8572, -663.0037) -> (-1891.8572, -670.7251)
  line L37 (-1931.8572, -663.0037) -> (-1891.8572, -663.0037)
  line L38 (-1931.8572, -670.7251) -> (-1931.8572, -663.0037)
  line L39 (-1981.2215, -675.0037) -> (-1936.1357, -675.0037)
  line L40 (-1985.5, -663.0037) -> (-1985.5, -670.7251)
  line L41 (-2025.5, -663.0037) -> (-1985.5, -663.0037)
  line L42 (-2025.5, -684.2546) -> (-2025.5, -663.0037)
  line L43 (-2017.7786, -684.2546) -> (-2025.5, -684.2546)
  line L44 (-1935.1142, -729.0627) -> (-1924.5451, -710.7716)
  line L45 (-1935.1168, -736.0627) -> (-1935.1142, -729.0627)
  line L46 (-1909.749, -736.0718) -> (-1935.1168, -736.0627)
  line L47 (-1987.3837, -783.585) -> (-1987.4012, -783.585)
  line L48 (-1974.8875, -761.9321) -> (-1987.3837, -783.585)
  line L49 (-1974.8888, -754.9321) -> (-1974.8875, -761.9321)
  line L50 (-2000.2462, -754.9366) -> (-1974.8888, -754.9321)
  line L51 (-1676.0651, -697.7014) -> (-1679.508, -697.7014)
  line L52 (-1671.7865, -733.4228) -> (-1671.7865, -701.98)
  line L53 (-1679.508, -737.7014) -> (-1676.0651, -737.7014)
  line L54 (-1683.7865, -701.98) -> (-1683.7865, -733.4228)
  line L55 (-1380.6843, -754.9321) -> (-1355.327, -754.9366)
  line L56 (-1380.6855, -761.9321) -> (-1380.6843, -754.9321)
  line L57 (-1368.1894, -783.585) -> (-1380.6855, -761.9321)
  line L58 (-1368.1719, -783.585) -> (-1368.1894, -783.585)
  line L59 (-1420.4563, -736.0627) -> (-1445.8241, -736.0718)
  line L60 (-1420.4588, -729.0627) -> (-1420.4563, -736.0627)
  line L61 (-1431.028, -710.7715) -> (-1420.4588, -729.0627)
  line L62 (-1347.327, -770.447) -> (-1368.1894, -783.585)
  line L63 (-1355.327, -754.9366) -> (-1347.327, -770.447)
  arc A1 centre (-2015.6393, -686.3939) radius 3.0254 clockwise from (-2017.7786, -684.2546) to (-2013.5, -688.5332)
  arc A2 centre (-2015.6393, -722.1154) radius 3.0254 clockwise from (-2013.5, -719.9761) to (-2017.7786, -724.2546)
  arc A3 centre (-1954.9982, -745.5055) radius 70.5018 clockwise from (-1954.9982, -816.0074) to (-2025.5, -745.5056)
  arc A4 centre (-1849.8686, -796.0074) radius 20 clockwise from (-1830.7023, -801.7217) to (-1849.8686, -816.0074)
  arc A5 centre (-1782.7866, -816.0074) radius 50 clockwise from (-1830.7023, -801.7217) to (-1782.7866, -766.0074)
  arc A6 centre (-1572.7866, -816.0074) radius 50 clockwise from (-1572.7866, -766.0074) to (-1524.8708, -801.7217)
  arc A7 centre (-1505.7045, -796.0074) radius 20 clockwise from (-1505.7045, -816.0074) to (-1524.8708, -801.7217)
  arc A8 centre (-1400.575, -745.5055) radius 70.5018 clockwise from (-1330.0731, -745.5055) to (-1400.575, -816.0074)
  arc A9 centre (-1339.9337, -722.1154) radius 3.0254 clockwise from (-1337.7945, -724.2546) to (-1342.073, -719.9761)
  arc A10 centre (-1339.9337, -686.3939) radius 3.0254 clockwise from (-1342.073, -688.5332) to (-1337.7945, -684.2546)
  arc A11 centre (-1327.9338, -677.143) radius 3.0254 clockwise from (-1330.0731, -679.2823) to (-1330, -674.933)
  arc A12 centre (-1372.1393, -672.8644) radius 3.0254 clockwise from (-1370, -670.7251) to (-1374.2786, -675.0037)
  arc A13 centre (-1421.5036, -672.8644) radius 3.0254 clockwise from (-1419.3643, -675.0037) to (-1423.6429, -670.7251)
  arc A14 centre (-1465.7822, -672.8644) radius 3.0254 clockwise from (-1463.6429, -670.7251) to (-1467.9214, -675.0037)
  arc A15 centre (-1515.1465, -672.8644) radius 3.0254 clockwise from (-1513.0072, -675.0037) to (-1517.2857, -670.7251)
  arc A16 centre (-1559.425, -672.8644) radius 3.0254 clockwise from (-1557.2857, -670.7251) to (-1561.5643, -675.0037)
  arc A17 centre (-1608.7893, -672.8644) radius 3.0254 clockwise from (-1606.65, -675.0037) to (-1610.9286, -670.7251)
  arc A18 centre (-1653.0679, -672.8644) radius 3.0254 clockwise from (-1650.9286, -670.7251) to (-1655.2072, -675.0037)
  arc A19 centre (-1702.4322, -672.8644) radius 3.0254 clockwise from (-1700.2929, -675.0037) to (-1704.5715, -670.7251)
  arc A20 centre (-1746.7107, -672.8644) radius 3.0254 clockwise from (-1744.5715, -670.7251) to (-1748.85, -675.0037)
  arc A21 centre (-1796.075, -672.8644) radius 3.0254 clockwise from (-1793.9358, -675.0037) to (-1798.2143, -670.7251)
  arc A22 centre (-1840.3536, -672.8644) radius 3.0254 clockwise from (-1838.2143, -670.7251) to (-1842.4929, -675.0037)
  arc A23 centre (-1889.7179, -672.8644) radius 3.0254 clockwise from (-1887.5786, -675.0037) to (-1891.8572, -670.7251)
  arc A24 centre (-1933.9965, -672.8644) radius 3.0254 clockwise from (-1931.8572, -670.7251) to (-1936.1357, -675.0037)
  arc A25 centre (-1983.3607, -672.8644) radius 3.0254 clockwise from (-1981.2215, -675.0037) to (-1985.5, -670.7251)
  arc A26 centre (-2002.1738, -752.6048) radius 3.0254 clockwise from (-2000.2462, -754.9366) to (-2004.7017, -750.9427)
  arc A27 centre (-1954.9982, -745.5055) radius 50 clockwise from (-2004.7017, -750.9427) to (-1925.8038, -704.9138)
  arc A28 centre (-1925.5877, -707.9315) radius 3.0254 clockwise from (-1925.8038, -704.9138) to (-1924.5451, -710.7716)
  arc A29 centre (-1907.8233, -738.4052) radius 3.0254 clockwise from (-1909.749, -736.0718) to (-1905.2949, -740.0665)
  arc A30 centre (-1954.9982, -745.5055) radius 50 clockwise from (-1905.2949, -740.0665) to (-1987.4012, -783.585)
  arc A31 centre (-1681.6472, -699.8407) radius 3.0254 clockwise from (-1683.7865, -701.98) to (-1679.508, -697.7014)
  arc A32 centre (-1673.9258, -699.8407) radius 3.0254 clockwise from (-1676.0651, -697.7014) to (-1671.7865, -701.98)
  arc A33 centre (-1673.9258, -735.5621) radius 3.0254 clockwise from (-1671.7865, -733.4228) to (-1676.0651, -737.7014)
  arc A34 centre (-1681.6472, -735.5621) radius 3.0254 clockwise from (-1679.508, -737.7014) to (-1683.7865, -733.4228)
  arc A35 centre (-1353.3994, -752.6048) radius 3.0254 clockwise from (-1350.8715, -750.9427) to (-1355.327, -754.9366)
  arc A36 centre (-1400.575, -745.5055) radius 50 clockwise from (-1368.1719, -783.585) to (-1450.2783, -740.0665)
  arc A37 centre (-1447.7498, -738.4052) radius 3.0254 clockwise from (-1450.2783, -740.0665) to (-1445.8241, -736.0718)
  arc A38 centre (-1429.9854, -707.9314) radius 3.0254 clockwise from (-1431.028, -710.7715) to (-1429.7693, -704.9138)
  arc A39 centre (-1400.575, -745.5055) radius 50 clockwise from (-1429.7693, -704.9138) to (-1350.8715, -750.9427)
  point P127 (-1368.1894, -783.585)
  point P137 (-1368.1894, -783.585)
  point P122 (-1355.327, -754.9366)
  point P139 (-1355.327, -754.9366)
  coincident P127 P137
  coincident P122 P139
extrude "Extrude3" add sketch "Sketch31" profile of L55 L56 L57 L62 L63 against normal blind 12
sketch "Sketch34" plane through (0, 0, 0) normal (0, -1, 0) x axis (1, 0, 0)
  line L1 (657.3281, 32.4224) -> (657.3106, 32.4224)
  line L2 (605.0437, 79.9447) -> (579.6759, 79.9356)
  line L3 (605.0412, 86.9447) -> (605.0437, 79.9447)
  line L4 (594.472, 105.2359) -> (605.0412, 86.9447)
  line L5 (644.8157, 61.0752) -> (670.1731, 61.0708)
  line L6 (644.8145, 54.0752) -> (644.8157, 61.0752)
  line L7 (657.3106, 32.4224) -> (644.8145, 54.0752)
  line L8 (12, 96.0313) -> (12, 127.4742)
  line L9 (0, 91.7528) -> (7.7214, 91.7528)
  line L10 (0, 70.5018) -> (0, 91.7528)
  line L11 (175.6314, 0) -> (70.5018, 0)
  line L12 (452.7135, 50) -> (242.7135, 50)
  line L13 (624.9251, 0) -> (519.7955, 0)
  line L14 (695.4269, 91.7528) -> (695.4269, 70.5018)
  line L15 (687.7056, 91.7528) -> (695.4269, 91.7528)
  line L16 (683.427, 127.4742) -> (683.427, 96.0313)
  line L17 (695.4269, 131.7528) -> (687.7056, 131.7528)
  line L18 (695.4269, 136.7251) -> (695.4269, 131.7528)
  line L19 (695.5, 153.0037) -> (695.5, 141.0744)
  line L20 (655.5, 153.0037) -> (695.5, 153.0037)
  line L21 (655.5, 145.2822) -> (655.5, 153.0037)
  line L22 (606.1357, 141.0037) -> (651.2214, 141.0037)
  line L23 (601.8571, 153.0037) -> (601.8571, 145.2822)
  line L24 (561.8571, 153.0037) -> (601.8571, 153.0037)
  line L25 (561.8571, 145.2822) -> (561.8571, 153.0037)
  line L26 (512.4928, 141.0037) -> (557.5786, 141.0037)
  line L27 (508.2143, 153.0037) -> (508.2143, 145.2822)
  line L28 (468.2143, 153.0037) -> (508.2143, 153.0037)
  line L29 (468.2143, 145.2822) -> (468.2143, 153.0037)
  line L30 (418.85, 141.0037) -> (463.9357, 141.0037)
  line L31 (414.5714, 153.0037) -> (414.5714, 145.2822)
  line L32 (374.5714, 153.0037) -> (414.5714, 153.0037)
  line L33 (374.5714, 145.2822) -> (374.5714, 153.0037)
  line L34 (325.2071, 141.0037) -> (370.2929, 141.0037)
  line L35 (320.9286, 153.0037) -> (320.9286, 145.2822)
  line L36 (280.9286, 153.0037) -> (320.9286, 153.0037)
  line L37 (280.9286, 145.2822) -> (280.9286, 153.0037)
  line L38 (231.5643, 141.0037) -> (276.65, 141.0037)
  line L39 (227.2857, 153.0037) -> (227.2857, 145.2822)
  line L40 (187.2857, 153.0037) -> (227.2857, 153.0037)
  line L41 (187.2857, 145.2822) -> (187.2857, 153.0037)
  line L42 (137.9214, 141.0037) -> (183.0072, 141.0037)
  line L43 (133.6429, 153.0037) -> (133.6429, 145.2822)
  line L44 (93.6429, 153.0037) -> (133.6429, 153.0037)
  line L45 (93.6429, 145.2822) -> (93.6429, 153.0037)
  line L46 (44.2786, 141.0037) -> (89.3643, 141.0037)
  line L47 (40, 153.0037) -> (40, 145.2822)
  line L48 (0, 153.0037) -> (40, 153.0037)
  line L49 (0, 131.7528) -> (0, 153.0037)
  line L50 (7.7214, 131.7528) -> (0, 131.7528)
  line L51 (90.3858, 86.9447) -> (100.955, 105.2358)
  line L52 (90.3833, 79.9447) -> (90.3858, 86.9447)
  line L53 (115.751, 79.9356) -> (90.3833, 79.9447)
  line L54 (38.1164, 32.4224) -> (38.0988, 32.4224)
  line L55 (50.6125, 54.0752) -> (38.1164, 32.4224)
  line L56 (50.6113, 61.0752) -> (50.6125, 54.0752)
  line L57 (25.2538, 61.0708) -> (50.6113, 61.0752)
  line L58 (349.4349, 118.306) -> (345.9921, 118.306)
  line L59 (353.7135, 82.5845) -> (353.7135, 114.0274)
  line L60 (345.9921, 78.306) -> (349.4349, 78.306)
  line L61 (341.7135, 114.0274) -> (341.7135, 82.5845)
  line L62 (657.3244, 32.3986) -> (657.3106, 32.4224)
  line L63 (657.3479, 32.4398) -> (657.3244, 32.3986)
  line L64 (657.3106, 32.4224) -> (657.3479, 32.4398)
  arc A1 centre (624.9251, 70.5018) radius 50 clockwise from (657.3281, 32.4224) to (575.2218, 75.9408)
  arc A2 centre (577.7502, 77.6022) radius 3.0254 clockwise from (575.2218, 75.9408) to (579.6759, 79.9356)
  arc A3 centre (595.5146, 108.0759) radius 3.0254 clockwise from (594.472, 105.2359) to (595.7308, 111.0936)
  arc A4 centre (624.9251, 70.5018) radius 50 clockwise from (595.7308, 111.0936) to (674.6286, 65.0647)
  arc A5 centre (672.1007, 63.4026) radius 3.0254 clockwise from (674.6286, 65.0647) to (670.1731, 61.0708)
  arc A6 centre (9.8607, 129.6135) radius 3.0254 clockwise from (7.7214, 131.7528) to (12, 127.4742)
  arc A7 centre (9.8607, 93.892) radius 3.0254 clockwise from (12, 96.0313) to (7.7214, 91.7528)
  arc A8 centre (70.5018, 70.5018) radius 70.5018 clockwise from (70.5018, 0) to (0, 70.5018)
  arc A9 centre (175.6314, 20) radius 20 clockwise from (194.7977, 14.2857) to (175.6314, 0)
  arc A10 centre (242.7135, 0) radius 50 clockwise from (194.7977, 14.2857) to (242.7135, 50)
  arc A11 centre (452.7135, 0) radius 50 clockwise from (452.7135, 50) to (500.6292, 14.2857)
  arc A12 centre (519.7955, 20) radius 20 clockwise from (519.7955, 0) to (500.6292, 14.2857)
  arc A13 centre (624.9251, 70.5018) radius 70.5018 clockwise from (695.4269, 70.5018) to (624.9251, 0)
  arc A14 centre (685.5663, 93.892) radius 3.0254 clockwise from (687.7056, 91.7528) to (683.427, 96.0313)
  arc A15 centre (685.5663, 129.6135) radius 3.0254 clockwise from (683.427, 127.4742) to (687.7056, 131.7528)
  arc A16 centre (697.5662, 138.8644) radius 3.0254 clockwise from (695.4269, 136.7251) to (695.5, 141.0744)
  arc A17 centre (653.3607, 143.143) radius 3.0254 clockwise from (655.5, 145.2822) to (651.2214, 141.0037)
  arc A18 centre (603.9964, 143.143) radius 3.0254 clockwise from (606.1357, 141.0037) to (601.8571, 145.2822)
  arc A19 centre (559.7179, 143.143) radius 3.0254 clockwise from (561.8571, 145.2822) to (557.5786, 141.0037)
  arc A20 centre (510.3536, 143.143) radius 3.0254 clockwise from (512.4928, 141.0037) to (508.2143, 145.2822)
  arc A21 centre (466.075, 143.143) radius 3.0254 clockwise from (468.2143, 145.2822) to (463.9357, 141.0037)
  arc A22 centre (416.7107, 143.143) radius 3.0254 clockwise from (418.85, 141.0037) to (414.5714, 145.2822)
  arc A23 centre (372.4321, 143.143) radius 3.0254 clockwise from (374.5714, 145.2822) to (370.2929, 141.0037)
  arc A24 centre (323.0679, 143.143) radius 3.0254 clockwise from (325.2071, 141.0037) to (320.9286, 145.2822)
  arc A25 centre (278.7893, 143.143) radius 3.0254 clockwise from (280.9286, 145.2822) to (276.65, 141.0037)
  arc A26 centre (229.425, 143.143) radius 3.0254 clockwise from (231.5643, 141.0037) to (227.2857, 145.2822)
  arc A27 centre (185.1464, 143.143) radius 3.0254 clockwise from (187.2857, 145.2822) to (183.0072, 141.0037)
  arc A28 centre (135.7821, 143.143) radius 3.0254 clockwise from (137.9214, 141.0037) to (133.6429, 145.2822)
  arc A29 centre (91.5036, 143.143) radius 3.0254 clockwise from (93.6429, 145.2822) to (89.3643, 141.0037)
  arc A30 centre (42.1393, 143.143) radius 3.0254 clockwise from (44.2786, 141.0037) to (40, 145.2822)
  arc A31 centre (23.3262, 63.4026) radius 3.0254 clockwise from (25.2538, 61.0708) to (20.7983, 65.0647)
  arc A32 centre (70.5018, 70.5018) radius 50 clockwise from (20.7983, 65.0647) to (99.6962, 111.0936)
  arc A33 centre (99.9124, 108.0759) radius 3.0254 clockwise from (99.6962, 111.0936) to (100.955, 105.2358)
  arc A34 centre (117.6767, 77.6022) radius 3.0254 clockwise from (115.751, 79.9356) to (120.2051, 75.9408)
  arc A35 centre (70.5018, 70.5018) radius 50 clockwise from (120.2051, 75.9408) to (38.0988, 32.4224)
  arc A36 centre (343.8528, 116.1667) radius 3.0254 clockwise from (341.7135, 114.0274) to (345.9921, 118.306)
  arc A37 centre (351.5742, 116.1667) radius 3.0254 clockwise from (349.4349, 118.306) to (353.7135, 114.0274)
  arc A38 centre (351.5742, 80.4453) radius 3.0254 clockwise from (353.7135, 82.5845) to (349.4349, 78.306)
  arc A39 centre (343.8528, 80.4453) radius 3.0254 clockwise from (345.9921, 78.306) to (341.7135, 82.5845)
  point P2 (657.3106, 32.4224)
  point P138 (657.3106, 32.4224)
  point P137 (657.3106, 32.4224)
  point P141 (657.3106, 32.4224)
  coincident P2 P138
  parallel L7 L62
  coincident P137 P141
extrude "Extrude4" add sketch "Sketch34" profile of L1 A1 L62 L63 L64 to an object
